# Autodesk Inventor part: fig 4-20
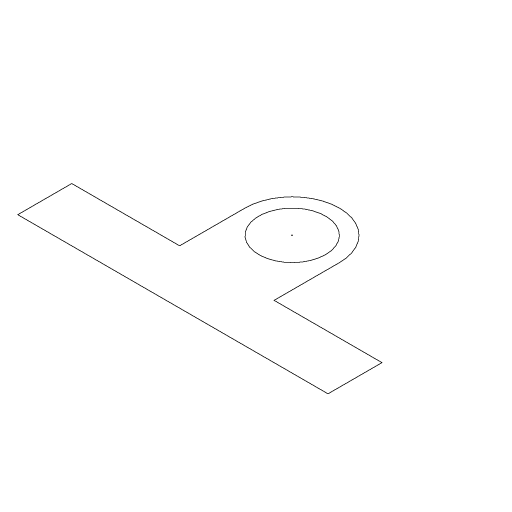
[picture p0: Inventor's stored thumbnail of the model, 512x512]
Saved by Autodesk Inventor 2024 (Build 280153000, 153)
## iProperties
Created: 2004-05
Part Number: fig 4-20
Document SubType Name: Modeling
Designer: CADCIM Technologies
Manufacturer: Standard
Standards Organization: Custom
Density: 1 g/cm^3
Material: Generic
Appearance: Default
Author: CADCIM Technologies
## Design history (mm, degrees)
sketch "Sketch1"
  geometry: L1 (21.396, 25)-(21.396, 15.181); L2 (21.396, 15.181)-(77.829, 15.181); L3 (77.829, 15.181)-(77.829, 25); L4 (77.829, 25)-(58.204, 25); L5 (58.204, 25)-(58.204, 36.886); L6 (41.021, 36.886)-(41.021, 25); L7 (41.021, 25)-(21.396, 25); C1 r 6.072 at (49.612, 36.886); A1 r 8.592 centre (49.612, 36.886) between (58.204, 36.886) and (41.021, 36.886)
  constraints: 14 end point, 5 parallel, 2 centre point, 2 equal length, 2 point on circle, 2 tangent, 1 coincident, 1 perpendicular, 1 vertical, 1 other
